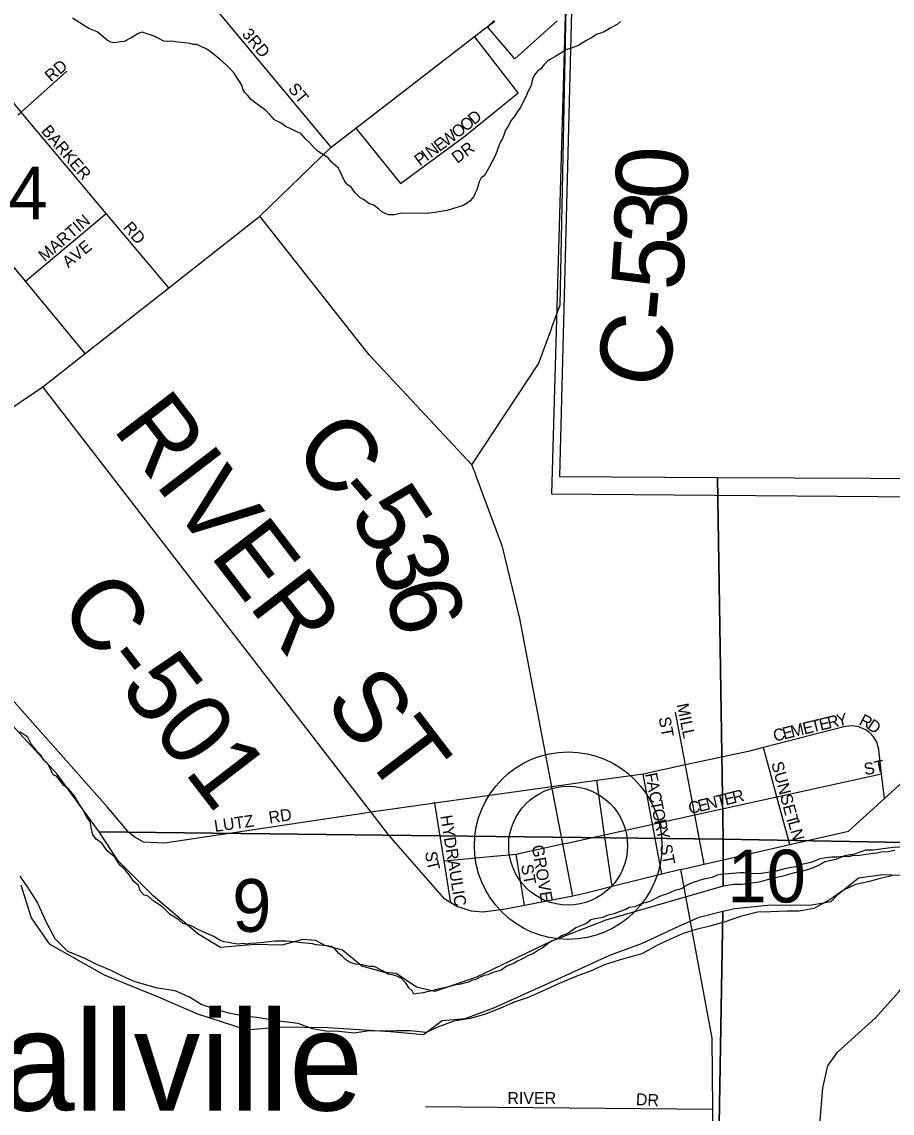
# Model space of a CAD drawing. Extents: x 1588073 to 2013523, y 1090242 to 1357120.
# Drawn here: x 1792474 to 1796119, y 1211790 to 1216361 of the extents above; entities that cross this region are included whole.
import ezdxf

# ---------------------------------------------------------------- set-up
doc = ezdxf.new("R2010")
doc.units = 0
for name, color, linetype in [('GM_X_Corporation', 7, 'Continuous'), ('GM_X_County_Road', 7, 'Continuous'), ('GM_X_County_Road_Text', 7, 'Continuous'), ('GM_X_County_Subdivision', 7, 'Continuous'), ('GM_X_County_Subdivision_Text', 7, 'Continuous'), ('GM_X_Major_River', 7, 'Continuous'), ('GM_X_Minor_River', 7, 'Continuous'), ('GM_X_Section', 7, 'Continuous'), ('GM_X_Section_Text', 7, 'Continuous'), ('GM_X_Township_Subdivision', 7, 'Continuous'), ('GM_X_Township_Subdivision_Text', 7, 'Continuous'), ('GM_X_Unincorporated', 7, 'Continuous'), ('GM_X_Unincorporated_Location', 7, 'Continuous'), ('GM_X_Unincorporated_Text', 7, 'Continuous')]:
    doc.layers.add(name, color=color, linetype=linetype)

msp = doc.modelspace()

# ---------------------------------------------------------------- linework, layer by layer
at = {"layer": 'GM_X_Corporation'}
for points in [[(1805453.2, 1214396.5), (1800906.6, 1214370.4), (1796742.8, 1214366.5), (1794693.8, 1214383.1), (1794758.1, 1216630.4)], [(1794715.7, 1216366), (1794538.2, 1216206.2), (1794423.8, 1216340.8), (1794452.4, 1216367.3)]]:
    msp.add_lwpolyline(points, dxfattribs=at)
at = {"layer": 'GM_X_County_Road'}
for points in [[(1794695.5, 1215084.6), (1794729.3, 1215175.9), (1794757.9, 1216629.7)], [(1789759.7, 1212989.5), (1790121.3, 1213253.9), (1790253.8, 1213350.8), (1790567, 1213531.6), (1791149.6, 1213911.9), (1791362.2, 1214046.3), (1791731, 1214279.2), (1791770.6, 1214304.2), (1791891.7, 1214380.7), (1792323.1, 1214671.5), (1792561.4, 1214832.2), (1792739.7, 1214972.4), (1793089.2, 1215247.2), (1793471.2, 1215547.7), (1793769.6, 1215836.8), (1793872.4, 1215916), (1794370.5, 1216299.8), (1794411.8, 1216331.6)], [(1794411.8, 1216331.6), (1794454.6, 1216364.6)], [(1794377.3, 1214457.9), (1794372.1, 1214471.8), (1794359.3, 1214506.3), (1793928.5, 1214966.6), (1793471.2, 1215547.7)], [(1794359.3, 1214506.3), (1794637.7, 1214928.2), (1794692.3, 1215075.9), (1794695.5, 1215084.6)], [(1794781.9, 1212698.1), (1794578.8, 1212659.6), (1794492.5, 1212643.3), (1794405.3, 1212631.2), (1794356.8, 1212635.8), (1794296.1, 1212655.3), (1794270.4, 1212671), (1794245.6, 1212686.2), (1794011.5, 1212953.8), (1793936.9, 1213050.4), (1792561.4, 1214832.2)], [(1794781.9, 1212698.1), (1794739.9, 1212917.5), (1794694.1, 1213156.7), (1794559.1, 1213862), (1794487, 1214161.8), (1794377.3, 1214457.9)], [(1795234.6, 1212810.7), (1795234.6, 1212810.7), (1795332.1, 1212833), (1795690.3, 1212915), (1795936.4, 1212971.4), (1796086.6, 1213107.6), (1796165.8, 1213179.3), (1796423.5, 1213411), (1796746.1, 1213692.1), (1797108.5, 1214017.9), (1797247.6, 1214192.2), (1797367, 1214386.8)], [(1795234.6, 1212810.7), (1795154.1, 1212790.7), (1794946.6, 1212739), (1794832.2, 1212710.6), (1794781.9, 1212698.1)], [(1795367.6, 1211805.9), (1795365.3, 1212103.6), (1795234.6, 1212810.7)], [(1795379, 1210300.3), (1795367.6, 1211805.9)]]:
    msp.add_lwpolyline(points, dxfattribs=at)
at = {"layer": 'GM_X_County_Subdivision'}
msp.add_lwpolyline([(1793769.6, 1215836.8), (1793287.1, 1216416), (1793289.2, 1216559.7), (1793296.6, 1217078.8), (1793296.6, 1217080.8)], dxfattribs=at)
at = {"layer": 'GM_X_Major_River'}
for points in [[(1794447.9, 1212379.6), (1794425.8, 1212369.8), (1794409.7, 1212365.9), (1794393.6, 1212360.1), (1794375.5, 1212350.2), (1794361.4, 1212346.4), (1794345.3, 1212338.5), (1794327.2, 1212334.7), (1794311.1, 1212330.8), (1794293, 1212327), (1794277, 1212323.1), (1794254.9, 1212317.3), (1794228.7, 1212311.6), (1794210.7, 1212307.8), (1794192.6, 1212301.9), (1794170.5, 1212298.1), (1794156.4, 1212294.3), (1794132.3, 1212290.5), (1794116.2, 1212288.6), (1794108.4, 1212302.8), (1794094.5, 1212314.9), (1794082.6, 1212335.1), (1794064.8, 1212353.3), (1794044.8, 1212363.5), (1794030.8, 1212367.7), (1794008.8, 1212371.9), (1793984.9, 1212386.2), (1793949, 1212404.6), (1793931, 1212404.7), (1793917, 1212406.9), (1793901, 1212411), (1793870.9, 1212413.3), (1793846.9, 1212421.6), (1793829, 1212433.8), (1793815.1, 1212448), (1793801.2, 1212458.1), (1793785.4, 1212478.3), (1793769.4, 1212488.5), (1793749.4, 1212490.7), (1793707.3, 1212495.1), (1793691.3, 1212499.3), (1793647.3, 1212503.7), (1793601.2, 1212508.2), (1793579.2, 1212510.4), (1793533.1, 1212510.9), (1793472.9, 1212503.5), (1793456.8, 1212501.6), (1793428.7, 1212499.9), (1793414.7, 1212498), (1793400.7, 1212500.2), (1793380.6, 1212498.3), (1793358.6, 1212500.6), (1793340.6, 1212504.8), (1793320.5, 1212507), (1793300.6, 1212515.2), (1793278.7, 1212529.4), (1793236.7, 1212547.9), (1793214.8, 1212558.1), (1793180.9, 1212576.5), (1793148.9, 1212584.8), (1793131, 1212599), (1793095.1, 1212621.4), (1793063.4, 1212653.8), (1793027.5, 1212676.2), (1793003.7, 1212698.5), (1792985.7, 1212702.7), (1792969.8, 1212720.9), (1792962, 1212743), (1792942.2, 1212761.2), (1792922.4, 1212791.5), (1792904.6, 1212811.7), (1792884.7, 1212828), (1792863, 1212862.2), (1792831.2, 1212888.6), (1792809.4, 1212920.9), (1792785.6, 1212937.2), (1792771.7, 1212955.4), (1792765.9, 1212981.5), (1792760.2, 1213009.6), (1792746.4, 1213029.8), (1792728.7, 1213062), (1792714.8, 1213082.2), (1792701, 1213106.4), (1792691.2, 1213122.5), (1792669.4, 1213148.8), (1792649.5, 1213163), (1792619.8, 1213199.4), (1792605.8, 1213207.6), (1792596, 1213227.7), (1792584.2, 1213249.9), (1792562.4, 1213272.1), (1792556.5, 1213286.2), (1792538.6, 1213304.4), (1792526.7, 1213320.6), (1792514.9, 1213334.7), (1792499.1, 1213365), (1792465.3, 1213387.3)], [(1796131, 1212890.2), (1796102.9, 1212884.4), (1796072.8, 1212882.7), (1796056.7, 1212878.9), (1796040.6, 1212877), (1796000.5, 1212871.4), (1795982.4, 1212869.6), (1795952.3, 1212867.9), (1795936.3, 1212864), (1795914.2, 1212864.3), (1795888.1, 1212862.5), (1795866.1, 1212862.7), (1795852, 1212860.9), (1795815.9, 1212855.2), (1795779.6, 1212839.5), (1795739.5, 1212831.9), (1795715.3, 1212822.1), (1795697.2, 1212818.3), (1795669.1, 1212812.6), (1795632.9, 1212802.9), (1795608.8, 1212799.1), (1795570.7, 1212793.5), (1795550.6, 1212791.7), (1795528.6, 1212793.9), (1795512.6, 1212794.1), (1795498.5, 1212796.2), (1795482.5, 1212796.3), (1795434.4, 1212792.8), (1795404.3, 1212789.1), (1795386.2, 1212787.3), (1795366, 1212777.4), (1795329.9, 1212769.8), (1795315.8, 1212765.9), (1795299.7, 1212760.1), (1795285.6, 1212756.2), (1795261.5, 1212746.4), (1795241.3, 1212732.6), (1795227.2, 1212726.7), (1795209.1, 1212722.9), (1795193, 1212715), (1795178.9, 1212709.1), (1795160.8, 1212703.3), (1795144.7, 1212697.4), (1795128.6, 1212689.6), (1795104.4, 1212675.8), (1795068.2, 1212666.1), (1795042.1, 1212654.4), (1795018, 1212650.6), (1795003.9, 1212642.7), (1794979.7, 1212634.9), (1794955.6, 1212625.1), (1794929.4, 1212619.4), (1794907.3, 1212609.6), (1794875.2, 1212603.9), (1794857.1, 1212600.1), (1794840.9, 1212586.2), (1794814.7, 1212574.4), (1794794.6, 1212566.6), (1794760.3, 1212542.9), (1794734.1, 1212533.1), (1794713.9, 1212517.3), (1794695.8, 1212511.4), (1794681.7, 1212503.6), (1794657.5, 1212483.8), (1794637.3, 1212471.9), (1794617.1, 1212458.1), (1794593, 1212448.3), (1794568.8, 1212434.5), (1794550.6, 1212426.7), (1794534.5, 1212416.8), (1794506.3, 1212407.1), (1794482.1, 1212389.3), (1794447.9, 1212379.6)], [(1796119.9, 1212784.1), (1796069.7, 1212772.5), (1796019.4, 1212759), (1795965.2, 1212747.5), (1795914.8, 1212723.9), (1795860.3, 1212684.4), (1795791.8, 1212647), (1795729.5, 1212635.6), (1795679.4, 1212636.1), (1795611.2, 1212632.7), (1795555, 1212631.3), (1795484.7, 1212613.9), (1795416.3, 1212590.5), (1795356, 1212573.1), (1795297.7, 1212559.6), (1795243.4, 1212542.1), (1795191.1, 1212518.6), (1795136.7, 1212493.1), (1795070.2, 1212457.6), (1794989.8, 1212434.4), (1794917.4, 1212413.1), (1794859, 1212385.6), (1794798.6, 1212364.1), (1794724.1, 1212332.8), (1794669.7, 1212307.2), (1794595.2, 1212273.9), (1794540.9, 1212256.4), (1794468.4, 1212225.1), (1794412.1, 1212203.6), (1794351.8, 1212186.1), (1794283.5, 1212174.8), (1794219.1, 1212151.3), (1794166.8, 1212127.8), (1794100.7, 1212134.5), (1794046.6, 1212135), (1793982.4, 1212133.6), (1793930.3, 1212134.1), (1793866, 1212124.8), (1793801.9, 1212131.4), (1793747.8, 1212133.9), (1793691.8, 1212142.5), (1793631.9, 1212165.1), (1793561.8, 1212173.8), (1793507.8, 1212182.4), (1793457.7, 1212190.9), (1793403.6, 1212195.4), (1793341.6, 1212208.1), (1793281.6, 1212224.7), (1793225.7, 1212245.3), (1793175.9, 1212275.9), (1793116, 1212302.5), (1793042, 1212313.3), (1792948, 1212340.2), (1792898.1, 1212362.8), (1792848.2, 1212387.3), (1792788.3, 1212412), (1792734.5, 1212438.6), (1792666.6, 1212467.3), (1792613, 1212519.9), (1792577.6, 1212588.4), (1792538.4, 1212675), (1792502.8, 1212729.5), (1792467.3, 1212782)]]:
    msp.add_lwpolyline(points, dxfattribs=at)
at = {"layer": 'GM_X_Minor_River'}
for points in [[(1793399.8, 1216079.3), (1793396.1, 1216093.4), (1793388.3, 1216107.5), (1793374.6, 1216127.8), (1793362.9, 1216146), (1793345.3, 1216166.3), (1793331.5, 1216180.6), (1793307.8, 1216201), (1793290.1, 1216215.3), (1793276.2, 1216225.5), (1793256.5, 1216241.8), (1793242.6, 1216250.1), (1793226.7, 1216256.3), (1793206.9, 1216266.7), (1793190.9, 1216266.9), (1793177, 1216271.1), (1793157, 1216273.4), (1793129, 1216275.8), (1793101.1, 1216280.3), (1793083.1, 1216278.6), (1793069.1, 1216280.8), (1793033.4, 1216299.3), (1793017.5, 1216305.6), (1793001.6, 1216309.8), (1792977.7, 1216318.2), (1792961.6, 1216312.5), (1792945.4, 1216302.7), (1792931.3, 1216294.9), (1792903, 1216279.3), (1792887, 1216277.5), (1792862.9, 1216273.8), (1792846.9, 1216276.1), (1792831.1, 1216284.3), (1792789.6, 1216319.1), (1792753.9, 1216333.6), (1792732.1, 1216348), (1792686.6, 1216376.8)], [(1794981.2, 1216362.2), (1794967, 1216350.4), (1794940.7, 1216336.8), (1794912.4, 1216319.1), (1794898.3, 1216313.3), (1794884.3, 1216309.5), (1794860, 1216293.8), (1794835.8, 1216282.2), (1794805.4, 1216262.6), (1794771.2, 1216249.1), (1794757.1, 1216245.3), (1794710.6, 1216217.9), (1794690.5, 1216206.2), (1794676.3, 1216196.4), (1794662, 1216182.6), (1794647.7, 1216164.7), (1794633.6, 1216154.9), (1794621.3, 1216139.1), (1794613, 1216121.1), (1794606.6, 1216095.2), (1794592, 1216065.3), (1794585.8, 1216049.4), (1794561, 1216001.6), (1794550.7, 1215985.7), (1794538.4, 1215967.9), (1794522, 1215946.1), (1794513.7, 1215928.1), (1794499.4, 1215908.3), (1794493, 1215886.3), (1794486.8, 1215872.4), (1794478.5, 1215858.5), (1794472.3, 1215842.5), (1794459.7, 1215806.6), (1794451.3, 1215788.7), (1794443.1, 1215774.8), (1794434.8, 1215756.9), (1794412.1, 1215717.1), (1794398, 1215707.3), (1794389.7, 1215691.4), (1794385.5, 1215677.4), (1794379.1, 1215657.5), (1794372.9, 1215643.5), (1794366.7, 1215629.6), (1794352.4, 1215611.8), (1794336.1, 1215600), (1794322, 1215592.2), (1794255.6, 1215571.1), (1794193.5, 1215562), (1794169.4, 1215558.4), (1794065.4, 1215560), (1794033.2, 1215552.4), (1794011.2, 1215552.8), (1793995.3, 1215559), (1793981.4, 1215565.2), (1793967.6, 1215577.5), (1793947.9, 1215593.8), (1793928, 1215600.1), (1793904.3, 1215616.5), (1793890.4, 1215624.8), (1793870.7, 1215645.1), (1793853.1, 1215669.4), (1793835.3, 1215681.7), (1793825.6, 1215695.9), (1793800.4, 1215748.4), (1793768.9, 1215775), (1793757.1, 1215791.2), (1793715.6, 1215817.9), (1793699.8, 1215832.1), (1793678.2, 1215856.5), (1793662.4, 1215870.8), (1793642.8, 1215893.2), (1793622.9, 1215901.5), (1793595.2, 1215915.9), (1793581.3, 1215922.1), (1793559.5, 1215936.5), (1793531.7, 1215951), (1793512.1, 1215973.3), (1793494.4, 1215991.6), (1793464.7, 1216012.1), (1793433.1, 1216036.7), (1793421.4, 1216050.9), (1793407.6, 1216065.1), (1793399.8, 1216079.3)]]:
    msp.add_lwpolyline(points, dxfattribs=at)
at = {"layer": 'GM_X_Section'}
for points in [[(1790239.7, 1218156.2), (1790948.4, 1218200.8), (1794819.6, 1218086.9), (1794726.1, 1214456.1), (1795388.4, 1214453.1), (1795411, 1212938.1), (1792797.7, 1212967.9), (1792621.5, 1213209.4), (1792307.9, 1213550), (1792091, 1213715.7), (1791925.4, 1213773), (1791803.2, 1213759.9), (1791549, 1213749.8), (1791352.8, 1213735.3), (1791188.4, 1213700.5), (1791053.9, 1213647.5), (1790844.8, 1213513), (1790758.4, 1213461.7), (1790659.9, 1213410.4), (1790364.7, 1213274.5), (1790199.9, 1213177.7), (1790167.6, 1213146)], [(1795411, 1212938.1), (1795411.5, 1212740.1), (1795160.8, 1212667.8), (1794920.1, 1212597.6), (1794689.3, 1212509.3), (1794378, 1212359.6), (1794203.5, 1212298.9), (1794127.6, 1212317.5), (1794041.9, 1212374.1), (1793993.9, 1212378.5), (1793898.1, 1212405.2), (1793816.6, 1212471.9), (1793742.7, 1212492.5), (1793704.8, 1212512.8), (1793650.8, 1212517.2), (1793562.6, 1212493.8), (1793450.5, 1212496.7), (1793306.4, 1212483.8), (1793210.7, 1212540.5), (1793023.8, 1212700.1), (1792876.9, 1212847.2), (1792797.7, 1212967.9)], [(1795411, 1212938.1), (1796317.3, 1212921.2), (1796254.9, 1212906), (1796237.2, 1212906), (1796212.5, 1212906), (1796173.6, 1212906), (1796124.1, 1212902.5), (1796039.2, 1212891.9), (1796007.4, 1212891.9), (1795961.4, 1212874.2), (1795919, 1212867.2), (1795883.7, 1212853), (1795837.7, 1212842.4), (1795812.9, 1212828.3), (1795781.1, 1212814.1), (1795745.8, 1212803.5), (1795710.4, 1212796.4), (1795660.9, 1212782.3), (1795611.4, 1212771.7), (1795561.9, 1212757.6), (1795491.2, 1212747), (1795455.9, 1212747), (1795411.5, 1212740.1)]]:
    msp.add_lwpolyline(points, close=True, dxfattribs=at)
for points in [[(1796317.3, 1212921.2), (1795411, 1212938.1), (1795388.4, 1214453.1), (1799241.5, 1214436.3)], [(1795325, 1207683.8), (1795410.7, 1212635.9), (1795460.8, 1212647.5), (1795597, 1212660.5), (1795781.1, 1212663.1), (1795863.2, 1212676.5), (1795891.5, 1212706.3), (1795978, 1212775.6), (1796080.2, 1212788.9), (1796228.3, 1212783.8)], [(1792469.9, 1212746.3), (1792512.9, 1212607.9), (1792588.1, 1212499.2), (1792819.2, 1212369.4), (1793044.7, 1212277.7), (1793210.2, 1212206.4), (1793415.8, 1212138.8), (1793554, 1212151.7), (1793756.1, 1212148.2), (1794018.1, 1212132.2), (1794156.1, 1212119.1), (1794234.6, 1212178.6), (1794330.7, 1212185.8), (1794451.1, 1212231), (1794736.2, 1212358.9), (1794937, 1212451.4), (1795073.5, 1212502.4), (1795226.1, 1212573.3), (1795310.4, 1212610.7), (1795410.7, 1212635.9), (1795325, 1207683.8)]]:
    msp.add_lwpolyline(points, dxfattribs=at)
at = {"layer": 'GM_X_Township_Subdivision'}
for points in [[(1793089.2, 1215247.2), (1792827.8, 1215558.2), (1792470.8, 1215983), (1792459.4, 1215996.5), (1792192, 1216318), (1792119.3, 1216405.4)], [(1793872.4, 1215916), (1794059.8, 1215684.6), (1794329.6, 1215882.5), (1794553.3, 1216064.6), (1794370.5, 1216299.8)], [(1792457.8, 1215971.5), (1792470.8, 1215983), (1792662.9, 1216154.5)], [(1792739.7, 1214972.4), (1792489.9, 1215274.7), (1792144.9, 1215692.3)], [(1792489.9, 1215274.7), (1792827.8, 1215558.2)], [(1793901.6, 1213045.2), (1793071.7, 1212921.1), (1792983.5, 1212925.4), (1792947.4, 1212945.6), (1792921.4, 1212965.7), (1792831.6, 1213072.4), (1792237.9, 1213742.3)], [(1795258.2, 1213224.3), (1795253.6, 1213248.6), (1795211.9, 1213468.9)], [(1796086.6, 1213107.6), (1796075, 1213211.1), (1796065.1, 1213299.5), (1796063.8, 1213313.2), (1796054.8, 1213343.6), (1796041.3, 1213366.5), (1796024.7, 1213383.8), (1796008.2, 1213395.8), (1795980.3, 1213407.8), (1795952.5, 1213412.1), (1795922.1, 1213409.2), (1795580.8, 1213321.9), (1795516.3, 1213305.3), (1795253.6, 1213248.6), (1795076.3, 1213210.3), (1794882.2, 1213183), (1794694.1, 1213156.7), (1794203.7, 1213087.9), (1793936.9, 1213050.4), (1793901.6, 1213045.2), (1793901.6, 1213045.2)], [(1795690.3, 1212915), (1795636.6, 1213114.7), (1795580.8, 1213321.9)], [(1795285.8, 1213077.5), (1795258.2, 1213224.3), (1795258.2, 1213224.3)], [(1794946.6, 1212739), (1794915.1, 1212956), (1794882.2, 1213183)], [(1795120.8, 1212970.5), (1795120.8, 1212970.5), (1795115.3, 1213000), (1795076.3, 1213210.3)], [(1795110.8, 1212999.1), (1795115.3, 1213000), (1795293.1, 1213039.1), (1795636.6, 1213114.7), (1796075, 1213211.1)], [(1794270.4, 1212671), (1794242.3, 1212846.8), (1794203.7, 1213087.9), (1794203, 1213092.2)], [(1795332.1, 1212833), (1795293.1, 1213039.1), (1795285.8, 1213077.5), (1795285.8, 1213077.5)], [(1794755.6, 1212920.9), (1794757.6, 1212921.4), (1794915.1, 1212956), (1795110.8, 1212999.1)], [(1795154.1, 1212790.7), (1795120.8, 1212970.5)], [(1794552.6, 1212876.3), (1794554.9, 1212876.8), (1794739.9, 1212917.5), (1794755.6, 1212920.9)], [(1794242.3, 1212846.8), (1794449.2, 1212865.8)], [(1794449.2, 1212865.8), (1794450.9, 1212866), (1794544.8, 1212874.6), (1794552.6, 1212876.3)], [(1794578.8, 1212659.6), (1794544.8, 1212874.6)], [(1795811.7, 1211530.5), (1795818.4, 1211758.7), (1795829, 1211895.2), (1795849.5, 1211987.5), (1795889.9, 1212045.6), (1796049.1, 1212189.6), (1796148, 1212299.7), (1796180.3, 1212347.2), (1796198.5, 1212373.9), (1796216.8, 1212434.1), (1796674.4, 1212435.4), (1796741.1, 1212389.7), (1796783.4, 1212336.8), (1796814.1, 1212266.3), (1796837.4, 1212064.9)], [(1794164.7, 1211817.8), (1795367.6, 1211805.9)]]:
    msp.add_lwpolyline(points, dxfattribs=at)
at = {"layer": 'GM_X_Unincorporated'}
for radius in [392.8, 249]:
    msp.add_circle((1794762.1, 1212910.3), radius, dxfattribs=at)
at = {"layer": 'GM_X_Unincorporated_Location'}
msp.add_line((1794762.1, 1212910.3), (1794762.1, 1212910.3), dxfattribs=at)

# ---------------------------------------------------------------- texts
at = {"layer": 'GM_X_County_Road_Text'}
for s, rotation, p in [('0', 88.5051, (1795259.9, 1215613.6)), ('3', 88.0109, (1795253.4, 1215426)), ('5', 86.1681, (1795240.5, 1215231.1)), ('-', 84.6255, (1795228.3, 1215099.7)), ('C', 74.5087, (1795152, 1214805.4)), ('RIVER', 307.5127, (1792850, 1214658)), ('C', 312.8828, (1793598.7, 1214556.1)), ('-', 311.089, (1793764.7, 1214377.4)), ('5', 303.4317, (1793839.3, 1214292.9)), ('3', 288.936, (1793932.3, 1214156.7)), ('C-501', 307.5853, (1792620.6, 1213907.5)), ('6', 285.1262, (1793990.7, 1213986.9)), ('ST', 307.4598, (1793734.5, 1213509.6))]:
    msp.add_text(s, height=300, rotation=rotation, dxfattribs=at).set_placement(p)
at = {"layer": 'GM_X_County_Subdivision_Text'}
for s, rotation, p in [('3RD', 310.3674, (1793392.8, 1216308.3)), ('ST', 309.8029, (1793586.5, 1216079.4))]:
    msp.add_text(s, height=50, rotation=rotation, dxfattribs=at).set_placement(p)
at = {"layer": 'GM_X_Section_Text'}
for s, p in [('4', (1792417.6, 1215534.2)), ('10', (1795429.4, 1212672.5)), ('9', (1793354.8, 1212549.3))]:
    msp.add_text(s, height=221, rotation=0, dxfattribs=at).set_placement(p)
at = {"layer": 'GM_X_Township_Subdivision_Text'}
for s, rotation, p in [('RD', 40.5994, (1792596.3, 1216106.9)), ('D', 40.0934, (1794368.4, 1215927.5)), ('BARKER', 310.6009, (1792551.9, 1215903.1)), ('O', 37.4499, (1794297.7, 1215871)), ('O', 39.7984, (1794334.4, 1215899.2)), ('E', 36.4585, (1794222.7, 1215815.5)), ('W', 36.4563, (1794251, 1215836.4)), ('N', 36.4459, (1794187.2, 1215789.4)), ('DR', 36.2542, (1794297.2, 1215766)), ('P', 36.4492, (1794141.2, 1215755.4)), ('I', 36.4511, (1794169.6, 1215776.3)), ('MARTIN', 40.6009, (1792569.9, 1215354.6)), ('RD', 310.6039, (1792895.1, 1215498.3)), ('AVE', 39.2897, (1792668.5, 1215327.7)), ('MILL', 281.6335, (1795216.4, 1213501.3)), ('ST', 280.6279, (1795140.7, 1213445.7)), ('E', 13.535, (1795819.9, 1213392.1)), ('R', 13.5297, (1795854.1, 1213400.3)), ('Y', 11.6979, (1795892.2, 1213409.5)), ('R', 332.7725, (1795976.9, 1213419.9)), ('C', 13.5297, (1795627.4, 1213345.8)), ('E', 13.5278, (1795665.9, 1213355)), ('M', 13.527, (1795700.1, 1213363.3)), ('E', 13.5278, (1795751.4, 1213375.6)), ('T', 13.5278, (1795785.7, 1213383.8)), ('D', 326.3979, (1796010.8, 1213402.5)), ('ST', 11.3113, (1796006.2, 1213205)), ('SUNSET', 285.0685, (1795612.4, 1213255.2)), ('F', 280.8572, (1795084.5, 1213210.8)), ('A', 280.862, (1795091.1, 1213176.2)), ('C', 280.8479, (1795099.4, 1213133)), ('T', 14.0412, (1795388.4, 1213070.4)), ('E', 14.0484, (1795422.6, 1213079)), ('R', 14.0304, (1795456.7, 1213087.5)), ('T', 280.8458, (1795106.9, 1213094.1)), ('C', 12.6934, (1795271.7, 1213042.3)), ('E', 13.8714, (1795311.4, 1213051.3)), ('N', 14.0329, (1795345.7, 1213059.8)), ('LUTZ', 8.1319, (1793283.1, 1212967.5)), ('RD', 8.9691, (1793511.8, 1213002.7)), ('HYDRAULIC', 279.1156, (1794226.6, 1213034.5)), ('O', 280.9486, (1795113.5, 1213059.5)), ('R', 282.3928, (1795122.2, 1213014.9)), ('LN', 284.7473, (1795682.7, 1213009)), ('Y', 283.2026, (1795130.8, 1212975.5)), ('GROVE', 279.4616, (1794609.5, 1212909.2)), ('ST', 280.6147, (1795146.1, 1212911.6)), ('S', 276.488, (1794163, 1212884.4)), ('T', 284.0041, (1794168.3, 1212842.4)), ('ST', 280.6135, (1794564.1, 1212827.7)), ('RIVER', 0, (1794507.6, 1211828)), ('DR', 356.9884, (1795044.9, 1211823.6))]:
    msp.add_text(s, height=50, rotation=rotation, dxfattribs=at).set_placement(p)
at = {"layer": 'GM_X_Unincorporated_Text'}
msp.add_text('Ballville', height=417, rotation=0, dxfattribs=at).set_placement((1792012.8, 1211800.8))

doc.saveas('drawing.dxf')
